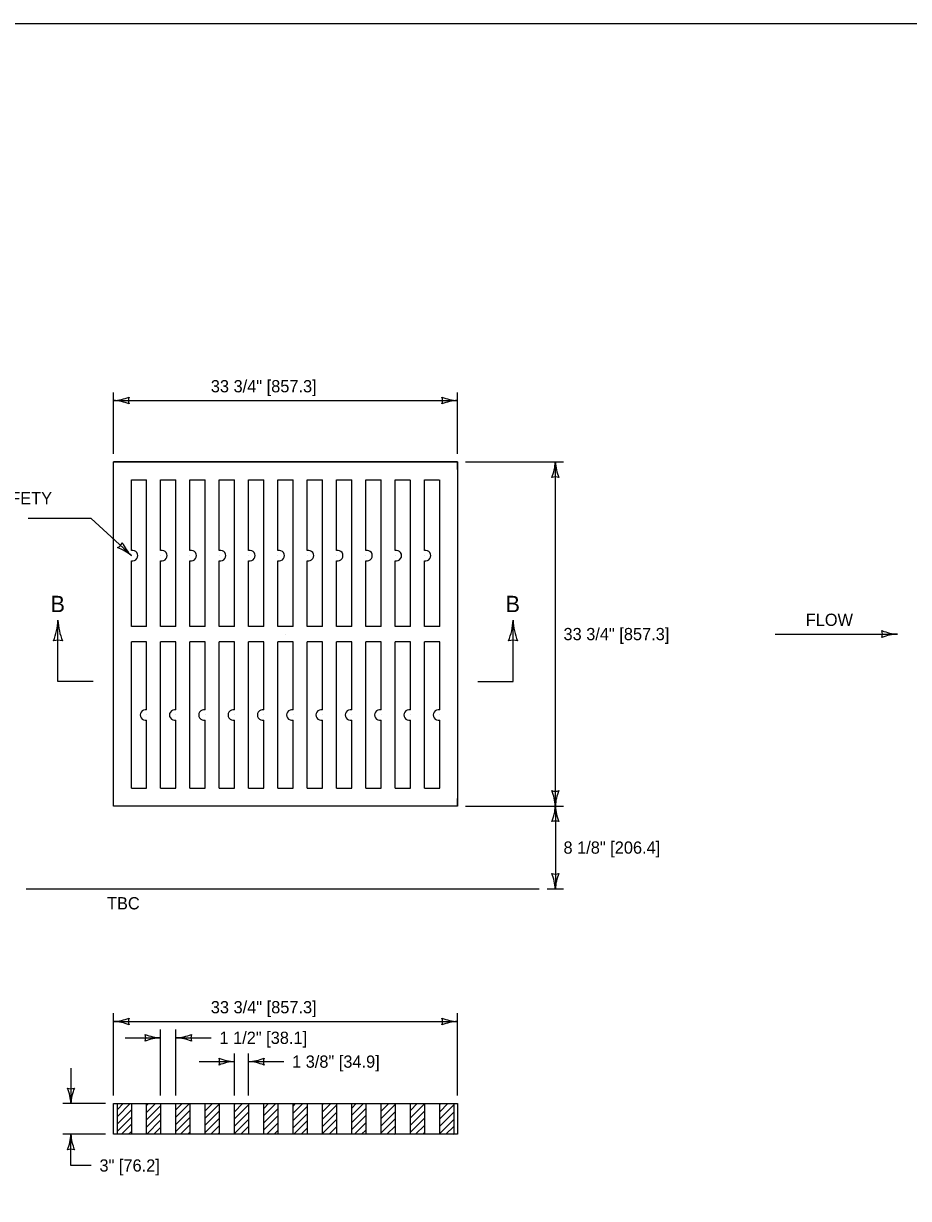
# Model space of a CAD drawing. Extents: x 49991.4 to 50041.6, y 49987.6 to 50011.4.
# Drawn here: x 50008.39 to 50012.74, y 49993.24 to 49999 of the extents above; entities that cross this region are included whole.
import ezdxf

# ---------------------------------------------------------------- set-up
doc = ezdxf.new("R2010")
doc.units = 0
for name, color, linetype in [('Level 1', 7, 'Continuous'), ('Level 2', 7, 'Continuous'), ('Level 3', 7, 'Continuous'), ('Level 6', 7, 'Continuous')]:
    doc.layers.add(name, color=color, linetype=linetype)

msp = doc.modelspace()

# ---------------------------------------------------------------- linework, layer by layer
at = {"layer": 'Level 1'}
for p, q in [((50010.5232, 49996.8492), (50008.8357, 49996.8492)), ((50008.8357, 49996.8117), (50008.8357, 49996.8492)), ((50008.8357, 49995.1617), (50008.8357, 49996.8492)), ((50008.8357, 49996.8492), (50010.5232, 49996.8492)), ((50010.5232, 49996.8117), (50010.5232, 49996.8492)), ((50010.5232, 49996.8492), (50010.5232, 49995.1617)), ((50008.9232, 49996.4149), (50008.9232, 49996.7617)), ((50008.9232, 49996.7617), (50008.9982, 49996.7617)), ((50008.9982, 49996.043), (50008.9982, 49996.7617)), ((50009.0669, 49996.4149), (50009.0669, 49996.7617)), ((50009.0669, 49996.7617), (50009.1419, 49996.7617)), ((50009.1419, 49996.043), (50009.1419, 49996.7617)), ((50009.2107, 49996.4149), (50009.2107, 49996.7617)), ((50009.2107, 49996.7617), (50009.2857, 49996.7617)), ((50009.2857, 49996.043), (50009.2857, 49996.7617)), ((50009.3544, 49996.4149), (50009.3544, 49996.7617)), ((50009.3544, 49996.7617), (50009.4294, 49996.7617)), ((50009.4294, 49996.043), (50009.4294, 49996.7617)), ((50009.4982, 49996.4149), (50009.4982, 49996.7617)), ((50009.4982, 49996.7617), (50009.5732, 49996.7617)), ((50009.5732, 49996.043), (50009.5732, 49996.7617)), ((50009.6419, 49996.4149), (50009.6419, 49996.7617)), ((50009.6419, 49996.7617), (50009.7169, 49996.7617)), ((50009.7169, 49996.043), (50009.7169, 49996.7617)), ((50009.7857, 49996.4149), (50009.7857, 49996.7617)), ((50009.7857, 49996.7617), (50009.8607, 49996.7617)), ((50009.8607, 49996.043), (50009.8607, 49996.7617)), ((50009.9294, 49996.4149), (50009.9294, 49996.7617)), ((50009.9294, 49996.7617), (50010.0044, 49996.7617)), ((50010.0044, 49996.043), (50010.0044, 49996.7617)), ((50010.0732, 49996.4149), (50010.0732, 49996.7617)), ((50010.0732, 49996.7617), (50010.1482, 49996.7617)), ((50010.1482, 49996.043), (50010.1482, 49996.7617)), ((50010.2169, 49996.4149), (50010.2169, 49996.7617)), ((50010.2169, 49996.7617), (50010.2888, 49996.7617)), ((50010.2919, 49996.043), (50010.2919, 49996.7617)), ((50010.3607, 49996.4149), (50010.3607, 49996.7617)), ((50010.3607, 49996.7617), (50010.4325, 49996.7617)), ((50010.4357, 49996.043), (50010.4357, 49996.7617)), ((50008.9232, 49996.3899), (50008.9232, 49996.3899)), ((50008.9232, 49996.043), (50008.9232, 49996.3649)), ((50009.0669, 49996.3899), (50009.0669, 49996.3899)), ((50009.0669, 49996.043), (50009.0669, 49996.3649)), ((50009.2107, 49996.3899), (50009.2107, 49996.3899)), ((50009.2107, 49996.043), (50009.2107, 49996.3649)), ((50009.3544, 49996.3899), (50009.3544, 49996.3899)), ((50009.3544, 49996.043), (50009.3544, 49996.3649)), ((50009.4982, 49996.3899), (50009.4982, 49996.3899)), ((50009.4982, 49996.043), (50009.4982, 49996.3649)), ((50009.6419, 49996.3899), (50009.6419, 49996.3899)), ((50009.6419, 49996.043), (50009.6419, 49996.3649)), ((50009.7857, 49996.3899), (50009.7857, 49996.3899)), ((50009.7857, 49996.043), (50009.7857, 49996.3649)), ((50009.9294, 49996.3899), (50009.9294, 49996.3899)), ((50009.9294, 49996.043), (50009.9294, 49996.3649)), ((50010.0732, 49996.3899), (50010.0732, 49996.3899)), ((50010.0732, 49996.043), (50010.0732, 49996.3649)), ((50010.2169, 49996.3899), (50010.2169, 49996.3899)), ((50010.2169, 49996.043), (50010.2169, 49996.3649)), ((50010.3607, 49996.3899), (50010.3607, 49996.3899)), ((50010.3607, 49996.043), (50010.3607, 49996.3649)), ((50008.9982, 49996.043), (50008.9232, 49996.043)), ((50009.1419, 49996.043), (50009.0669, 49996.043)), ((50009.2857, 49996.043), (50009.2107, 49996.043)), ((50009.4294, 49996.043), (50009.3544, 49996.043)), ((50009.5732, 49996.043), (50009.4982, 49996.043)), ((50009.7169, 49996.043), (50009.6419, 49996.043)), ((50009.6794, 49996.0055), (50009.6794, 49996.0055)), ((50009.8607, 49996.043), (50009.7857, 49996.043)), ((50010.0044, 49996.043), (50009.9294, 49996.043)), ((50010.1482, 49996.043), (50010.0732, 49996.043)), ((50010.2919, 49996.043), (50010.2169, 49996.043)), ((50010.4357, 49996.043), (50010.3607, 49996.043)), ((50008.9232, 49995.2492), (50008.9232, 49995.968)), ((50008.9982, 49995.968), (50008.9232, 49995.968)), ((50008.9982, 49995.6336), (50008.9982, 49995.968)), ((50009.0669, 49995.2492), (50009.0669, 49995.968)), ((50009.1419, 49995.968), (50009.0669, 49995.968)), ((50009.1419, 49995.6336), (50009.1419, 49995.968)), ((50009.2107, 49995.2492), (50009.2107, 49995.968)), ((50009.2857, 49995.968), (50009.2107, 49995.968)), ((50009.2857, 49995.6336), (50009.2857, 49995.968)), ((50009.3544, 49995.2492), (50009.3544, 49995.968)), ((50009.4294, 49995.968), (50009.3544, 49995.968)), ((50009.4294, 49995.6336), (50009.4294, 49995.968)), ((50009.4982, 49995.2492), (50009.4982, 49995.968)), ((50009.5732, 49995.968), (50009.4982, 49995.968)), ((50009.5732, 49995.6336), (50009.5732, 49995.968)), ((50009.6419, 49995.2492), (50009.6419, 49995.968)), ((50009.7169, 49995.968), (50009.6419, 49995.968)), ((50009.7169, 49995.6336), (50009.7169, 49995.968)), ((50009.7857, 49995.2492), (50009.7857, 49995.968)), ((50009.8607, 49995.968), (50009.7857, 49995.968)), ((50009.8607, 49995.6336), (50009.8607, 49995.968)), ((50009.9294, 49995.2492), (50009.9294, 49995.968)), ((50010.0044, 49995.968), (50009.9294, 49995.968)), ((50010.0044, 49995.6336), (50010.0044, 49995.968)), ((50010.0732, 49995.2492), (50010.0732, 49995.968)), ((50010.1482, 49995.968), (50010.0732, 49995.968)), ((50010.1482, 49995.6336), (50010.1482, 49995.968)), ((50010.2169, 49995.2492), (50010.2169, 49995.968)), ((50010.2919, 49995.968), (50010.2169, 49995.968)), ((50010.2919, 49995.6336), (50010.2919, 49995.968)), ((50010.3607, 49995.2492), (50010.3607, 49995.968)), ((50010.4357, 49995.968), (50010.3607, 49995.968)), ((50010.4357, 49995.6336), (50010.4357, 49995.968)), ((50008.9982, 49995.6086), (50008.9982, 49995.6086)), ((50009.1419, 49995.6086), (50009.1419, 49995.6086)), ((50009.2857, 49995.6086), (50009.2857, 49995.6086)), ((50009.4294, 49995.6086), (50009.4294, 49995.6086)), ((50009.5732, 49995.6086), (50009.5732, 49995.6086)), ((50009.7169, 49995.6086), (50009.7169, 49995.6086)), ((50009.8607, 49995.6086), (50009.8607, 49995.6086)), ((50010.0044, 49995.6086), (50010.0044, 49995.6086)), ((50010.1482, 49995.6086), (50010.1482, 49995.6086)), ((50010.2919, 49995.6086), (50010.2919, 49995.6086)), ((50010.4357, 49995.6086), (50010.4357, 49995.6086)), ((50008.9982, 49995.2492), (50008.9982, 49995.5836)), ((50009.1419, 49995.2492), (50009.1419, 49995.5836)), ((50009.2857, 49995.2492), (50009.2857, 49995.5836)), ((50009.4294, 49995.2492), (50009.4294, 49995.5836)), ((50009.5732, 49995.2492), (50009.5732, 49995.5836)), ((50009.7169, 49995.2492), (50009.7169, 49995.5836)), ((50009.8607, 49995.2492), (50009.8607, 49995.5836)), ((50010.0044, 49995.2492), (50010.0044, 49995.5836)), ((50010.1482, 49995.2492), (50010.1482, 49995.5836)), ((50010.2919, 49995.2492), (50010.2919, 49995.5836)), ((50010.4357, 49995.2492), (50010.4357, 49995.5836)), ((50008.8357, 49995.1617), (50008.8357, 49995.1992)), ((50008.9232, 49995.2492), (50008.9982, 49995.2492)), ((50009.0669, 49995.2492), (50009.1419, 49995.2492)), ((50009.2107, 49995.2492), (50009.2857, 49995.2492)), ((50009.3544, 49995.2492), (50009.4294, 49995.2492)), ((50009.4982, 49995.2492), (50009.5732, 49995.2492)), ((50009.6419, 49995.2492), (50009.7169, 49995.2492)), ((50009.7857, 49995.2492), (50009.8607, 49995.2492)), ((50009.9294, 49995.2492), (50010.0044, 49995.2492)), ((50010.0732, 49995.2492), (50010.1482, 49995.2492)), ((50010.2169, 49995.2492), (50010.2919, 49995.2492)), ((50010.3607, 49995.2492), (50010.4357, 49995.2492)), ((50010.5232, 49995.1617), (50010.5232, 49995.1992)), ((50010.5232, 49995.1617), (50008.8357, 49995.1617)), ((50010.5232, 49995.1617), (50008.8357, 49995.1617)), ((50008.4069, 49994.7555), (50010.9232, 49994.7555)), ((50008.8357, 49993.703), (50010.5232, 49993.703)), ((50008.8357, 49993.553), (50008.8357, 49993.703)), ((50008.8544, 49993.6393), (50008.9181, 49993.703)), ((50008.8544, 49993.6746), (50008.8828, 49993.703)), ((50008.9982, 49993.6589), (50009.0422, 49993.703)), ((50008.9982, 49993.6943), (50009.0069, 49993.703)), ((50009.1419, 49993.6365), (50009.2084, 49993.703)), ((50009.1419, 49993.6719), (50009.173, 49993.703)), ((50009.2857, 49993.6675), (50009.3211, 49993.703)), ((50009.2857, 49993.7029), (50009.2857, 49993.703)), ((50009.2857, 49993.6322), (50009.3544, 49993.7009)), ((50009.4294, 49993.6633), (50009.469, 49993.703)), ((50009.4294, 49993.6987), (50009.4337, 49993.703)), ((50009.4294, 49993.628), (50009.4982, 49993.6967)), ((50009.5732, 49993.6445), (50009.6316, 49993.703)), ((50009.5732, 49993.6799), (50009.5963, 49993.703)), ((50009.7169, 49993.6555), (50009.7644, 49993.703)), ((50009.7169, 49993.6908), (50009.729, 49993.703)), ((50009.8607, 49993.6623), (50009.9014, 49993.703)), ((50009.8607, 49993.6976), (50009.866, 49993.703)), ((50009.8607, 49993.6269), (50009.9294, 49993.6957)), ((50010.0044, 49993.6461), (50010.0613, 49993.703)), ((50010.0044, 49993.6814), (50010.0259, 49993.703)), ((50010.1482, 49993.6653), (50010.1858, 49993.703)), ((50010.1482, 49993.7006), (50010.1505, 49993.703)), ((50010.1482, 49993.6299), (50010.2169, 49993.6987)), ((50010.2919, 49993.6688), (50010.3261, 49993.703)), ((50010.2919, 49993.6334), (50010.3607, 49993.7022)), ((50010.4357, 49993.6633), (50010.4753, 49993.703)), ((50010.4357, 49993.6987), (50010.4399, 49993.703)), ((50010.4357, 49993.628), (50010.5044, 49993.6967)), ((50010.5232, 49993.703), (50010.5232, 49993.553)), ((50008.8544, 49993.6039), (50008.9232, 49993.6727)), ((50008.9982, 49993.6235), (50009.0669, 49993.6923)), ((50008.9982, 49993.5882), (50009.0669, 49993.6569)), ((50009.1419, 49993.6012), (50009.2107, 49993.6699)), ((50009.2857, 49993.5968), (50009.3544, 49993.6656)), ((50009.4294, 49993.5926), (50009.4982, 49993.6614)), ((50009.5732, 49993.6091), (50009.6419, 49993.6779)), ((50009.5732, 49993.5738), (50009.6419, 49993.6425)), ((50009.7169, 49993.6201), (50009.7857, 49993.6889)), ((50009.7169, 49993.5848), (50009.7857, 49993.6535)), ((50009.8607, 49993.5916), (50009.9294, 49993.6603)), ((50010.0044, 49993.6107), (50010.0732, 49993.6795)), ((50010.0044, 49993.5754), (50010.0732, 49993.6441)), ((50010.1482, 49993.5946), (50010.2169, 49993.6633)), ((50010.2919, 49993.5981), (50010.3607, 49993.6668)), ((50010.4357, 49993.5926), (50010.5044, 49993.6614)), ((50008.8544, 49993.5685), (50008.9232, 49993.6373)), ((50008.8742, 49993.553), (50008.9232, 49993.6019)), ((50008.9983, 49993.553), (50009.0669, 49993.6216)), ((50009.0336, 49993.553), (50009.0669, 49993.5862)), ((50009.1419, 49993.5658), (50009.2107, 49993.6345)), ((50009.1644, 49993.553), (50009.2107, 49993.5992)), ((50009.2857, 49993.5615), (50009.3544, 49993.6302)), ((50009.3125, 49993.553), (50009.3544, 49993.5949)), ((50009.4294, 49993.5573), (50009.4982, 49993.626)), ((50009.4605, 49993.553), (50009.4982, 49993.5907)), ((50009.5877, 49993.553), (50009.6419, 49993.6072)), ((50009.7205, 49993.553), (50009.7857, 49993.6182)), ((50009.7558, 49993.553), (50009.7857, 49993.5828)), ((50009.8607, 49993.5562), (50009.9294, 49993.625)), ((50009.8928, 49993.553), (50009.9294, 49993.5896)), ((50010.0174, 49993.553), (50010.0732, 49993.6088)), ((50010.1482, 49993.5592), (50010.2169, 49993.628)), ((50010.1773, 49993.553), (50010.2169, 49993.5926)), ((50010.2919, 49993.5627), (50010.3607, 49993.6315)), ((50010.3175, 49993.553), (50010.3607, 49993.5961)), ((50010.4357, 49993.5573), (50010.5044, 49993.626)), ((50010.4667, 49993.553), (50010.5044, 49993.5907)), ((50010.5232, 49993.553), (50008.8357, 49993.553)), ((50008.9095, 49993.553), (50008.9232, 49993.5666)), ((50009.1998, 49993.553), (50009.2107, 49993.5638)), ((50009.3479, 49993.553), (50009.3544, 49993.5595)), ((50009.4958, 49993.553), (50009.4982, 49993.5553)), ((50009.623, 49993.553), (50009.6419, 49993.5718)), ((50009.9281, 49993.553), (50009.9294, 49993.5542)), ((50010.0527, 49993.553), (50010.0732, 49993.5734)), ((50010.2126, 49993.553), (50010.2169, 49993.5573)), ((50010.3529, 49993.553), (50010.3607, 49993.5608)), ((50010.5021, 49993.553), (50010.5044, 49993.5553))]:
    msp.add_line(p, q, dxfattribs=at)
for points in [[(49999.3835, 49998.9992), (50016.7501, 49998.9992), (50016.7501, 49987.7988), (49999.3835, 49987.7988)], [(50008.8544, 49993.703), (50008.9232, 49993.703), (50008.9232, 49993.553), (50008.8544, 49993.553)], [(50008.9982, 49993.703), (50009.0669, 49993.703), (50009.0669, 49993.553), (50008.9982, 49993.553)], [(50009.1419, 49993.703), (50009.2107, 49993.703), (50009.2107, 49993.553), (50009.1419, 49993.553)], [(50009.2857, 49993.703), (50009.3544, 49993.703), (50009.3544, 49993.553), (50009.2857, 49993.553)], [(50009.4294, 49993.703), (50009.4982, 49993.703), (50009.4982, 49993.553), (50009.4294, 49993.553)], [(50009.5732, 49993.703), (50009.6419, 49993.703), (50009.6419, 49993.553), (50009.5732, 49993.553)], [(50009.7169, 49993.703), (50009.7857, 49993.703), (50009.7857, 49993.553), (50009.7169, 49993.553)], [(50009.8607, 49993.703), (50009.9294, 49993.703), (50009.9294, 49993.553), (50009.8607, 49993.553)], [(50010.0044, 49993.703), (50010.0732, 49993.703), (50010.0732, 49993.553), (50010.0044, 49993.553)], [(50010.1482, 49993.703), (50010.2169, 49993.703), (50010.2169, 49993.553), (50010.1482, 49993.553)], [(50010.2919, 49993.703), (50010.3607, 49993.703), (50010.3607, 49993.553), (50010.2919, 49993.553)], [(50010.4357, 49993.703), (50010.5044, 49993.703), (50010.5044, 49993.553), (50010.4357, 49993.553)]]:
    msp.add_lwpolyline(points, close=True, dxfattribs=at)
for centre, start, end in [((50008.9293, 49996.3899), 256.09409, 103.90591), ((50009.0731, 49996.3899), 256.09409, 103.90591), ((50009.2168, 49996.3899), 256.09409, 103.90591), ((50009.3606, 49996.3899), 256.09409, 103.90591), ((50009.5043, 49996.3899), 256.09409, 103.90591), ((50009.6481, 49996.3899), 256.09409, 103.90591), ((50009.7918, 49996.3899), 256.09409, 103.90591), ((50009.9356, 49996.3899), 256.09409, 103.90591), ((50010.0793, 49996.3899), 256.09409, 103.90591), ((50010.2231, 49996.3899), 256.09409, 103.90591), ((50010.3668, 49996.3899), 256.09409, 103.90591), ((50008.992, 49995.6086), 76.09409, 283.90591), ((50009.1357, 49995.6086), 76.09409, 283.90591), ((50009.2795, 49995.6086), 76.09409, 283.90591), ((50009.4232, 49995.6086), 76.09409, 283.90591), ((50009.567, 49995.6086), 76.09409, 283.90591), ((50009.7107, 49995.6086), 76.09409, 283.90591), ((50009.8545, 49995.6086), 76.09409, 283.90591), ((50009.9982, 49995.6086), 76.09409, 283.90591), ((50010.142, 49995.6086), 76.09409, 283.90591), ((50010.2857, 49995.6086), 76.09409, 283.90591), ((50010.4295, 49995.6086), 76.09409, 283.90591)]:
    msp.add_arc(centre, 0.0258, start, end, dxfattribs=at)
at = {"layer": 'Level 3'}
for p, q in [((50008.8357, 49996.8892), (50008.8357, 49997.1907)), ((50010.5232, 49996.8892), (50010.5232, 49997.1907)), ((50008.8357, 49997.1507), (50010.5232, 49997.1507)), ((50010.5632, 49996.8492), (50011.0432, 49996.8492)), ((50011.0032, 49995.1617), (50011.0032, 49996.8492)), ((50008.7265, 49996.5716), (50008.4169, 49996.5716)), ((50008.9232, 49996.3899), (50008.7265, 49996.5716)), ((50012.0814, 49996.0055), (50012.6814, 49996.0055)), ((50010.5632, 49995.1617), (50011.0432, 49995.1617)), ((50011.0032, 49995.1617), (50011.0032, 49994.7555)), ((50010.9632, 49994.7555), (50011.0432, 49994.7555)), ((50008.8357, 49993.743), (50008.8357, 49994.1459)), ((50008.8357, 49994.1059), (50010.5232, 49994.1059)), ((50010.5232, 49993.743), (50010.5232, 49994.1459)), ((50009.0669, 49993.743), (50009.0669, 49994.0659)), ((50009.1419, 49993.743), (50009.1419, 49994.0659)), ((50008.8935, 49994.0259), (50009.0669, 49994.0259)), ((50009.1419, 49994.0259), (50009.3153, 49994.0259)), ((50009.4294, 49993.743), (50009.4294, 49993.9491)), ((50009.4982, 49993.743), (50009.4982, 49993.9491)), ((50008.6267, 49993.8764), (50008.6267, 49993.703)), ((50009.256, 49993.9091), (50009.4294, 49993.9091)), ((50009.4982, 49993.9091), (50009.6716, 49993.9091)), ((50008.7957, 49993.703), (50008.5867, 49993.703)), ((50008.7957, 49993.553), (50008.5867, 49993.553)), ((50008.6267, 49993.3995), (50008.6267, 49993.553)), ((50008.7267, 49993.3995), (50008.6267, 49993.3995))]:
    msp.add_line(p, q, dxfattribs=at)
for centre, radius, start, end in [((50008.8242, 49997.3834), 0.233, 272.82731, 292.07716), ((50008.9639, 49997.1507), 0.0548, 162.13882, 197.86118), ((50010.5323, 49997.3728), 0.2223, 247.45601, 267.63952), ((50010.3949, 49997.1507), 0.0548, 342.13882, 17.86118), ((50008.8265, 49996.9285), 0.2223, 67.45601, 87.63952), ((50010.5346, 49996.918), 0.233, 92.82731, 112.07716), ((50010.781, 49996.8584), 0.2223, 337.45601, 357.63952), ((50011.2359, 49996.8607), 0.233, 182.82731, 202.07716), ((50011.0032, 49996.721), 0.0548, 72.13882, 107.86118), ((50008.829, 49996.4769), 0.0548, 299.41223, 335.13459), ((50008.7737, 49996.2111), 0.233, 50.10072, 69.35057), ((50009.0806, 49996.5468), 0.2223, 204.72942, 224.91293), ((50012.6906, 49996.2276), 0.2223, 247.45601, 267.63952), ((50012.5532, 49996.0055), 0.0548, 342.13882, 17.86118), ((50012.6929, 49995.7728), 0.233, 92.82731, 112.07716), ((50011.0032, 49995.29), 0.0548, 252.13882, 287.86118), ((50010.7704, 49995.1503), 0.233, 2.82731, 22.07716), ((50011.2253, 49995.1526), 0.2223, 157.45601, 177.63952), ((50010.781, 49995.1709), 0.2223, 337.45601, 357.63952), ((50011.2359, 49995.1732), 0.233, 182.82731, 202.07716), ((50011.0032, 49995.0335), 0.0548, 72.13882, 107.86118), ((50011.0032, 49994.8837), 0.0548, 252.13882, 287.86118), ((50010.7704, 49994.744), 0.233, 2.82731, 22.07716), ((50011.2253, 49994.7463), 0.2223, 157.45601, 177.63952), ((50008.8242, 49994.3386), 0.233, 272.82731, 292.07716), ((50008.8265, 49993.8837), 0.2223, 67.45601, 87.63952), ((50008.9639, 49994.1059), 0.0548, 162.13882, 197.86118), ((50010.5323, 49994.328), 0.2223, 247.45601, 267.63952), ((50010.3949, 49994.1059), 0.0548, 342.13882, 17.86118), ((50010.5346, 49993.8731), 0.233, 92.82731, 112.07716), ((50009.0761, 49994.248), 0.2223, 247.45601, 267.63952), ((50008.9387, 49994.0259), 0.0548, 342.13882, 17.86118), ((50009.1304, 49994.2586), 0.233, 272.82731, 292.07716), ((50009.2701, 49994.0259), 0.0548, 162.13882, 197.86118), ((50009.0784, 49993.7931), 0.233, 92.82731, 112.07716), ((50009.1327, 49993.8037), 0.2223, 67.45601, 87.63952), ((50009.4386, 49994.1312), 0.2223, 247.45601, 267.63952), ((50009.3012, 49993.9091), 0.0548, 342.13882, 17.86118), ((50009.4867, 49994.1418), 0.233, 272.82731, 292.07716), ((50009.6264, 49993.9091), 0.0548, 162.13882, 197.86118), ((50009.4409, 49993.6764), 0.233, 92.82731, 112.07716), ((50009.489, 49993.6869), 0.2223, 67.45601, 87.63952), ((50008.6267, 49993.8312), 0.0548, 252.13882, 287.86118), ((50008.394, 49993.6915), 0.233, 2.82731, 22.07716), ((50008.8489, 49993.6938), 0.2223, 157.45601, 177.63952), ((50008.4046, 49993.5621), 0.2223, 337.45601, 357.63952), ((50008.8594, 49993.5645), 0.233, 182.82731, 202.07716), ((50008.6267, 49993.4247), 0.0548, 72.13882, 107.86118)]:
    msp.add_arc(centre, radius, start, end, dxfattribs=at)
at = {"layer": 'Level 6'}
for p, q in [((50008.5632, 49995.773), (50008.5632, 49996.073)), ((50010.7957, 49995.773), (50010.7957, 49996.073)), ((50008.7357, 49995.773), (50008.5632, 49995.773)), ((50010.6232, 49995.773), (50010.7957, 49995.773))]:
    msp.add_line(p, q, dxfattribs=at)
for centre, radius, start, end in [((50008.267, 49996.0852), 0.2964, 337.45601, 357.63952), ((50008.8734, 49996.0883), 0.3107, 182.82731, 202.07716), ((50010.4995, 49996.0852), 0.2964, 337.45601, 357.63952), ((50011.1059, 49996.0883), 0.3107, 182.82731, 202.07716), ((50008.5632, 49995.902), 0.073, 72.13882, 107.86118), ((50010.7957, 49995.902), 0.073, 72.13882, 107.86118)]:
    msp.add_arc(centre, radius, start, end, dxfattribs=at)

# ---------------------------------------------------------------- texts
at = {"layer": 'Level 2'}
for s, height, p in [('33 3/4" [857.3]', 0.06, (50009.313, 49997.1907)), ('SAFETY', 0.06, (50008.2221, 49996.6418)), ('B', 0.08, (50008.5261, 49996.113)), ('B', 0.08, (50010.7586, 49996.113)), ('FLOW', 0.06, (50012.2316, 49996.0455)), ('33 3/4" [857.3]', 0.06, (50011.0432, 49995.9755)), ('8 1/8" [206.4]', 0.06, (50011.0432, 49994.9286)), ('TBC', 0.06, (50008.8037, 49994.6555)), ('33 3/4" [857.3]', 0.06, (50009.313, 49994.1459)), ('1 1/2" [38.1]', 0.06, (50009.3553, 49993.9959)), ('1 3/8" [34.9]', 0.06, (50009.7116, 49993.8791)), ('3" [76.2]', 0.06, (50008.7667, 49993.3697))]:
    msp.add_text(s, height=height, dxfattribs=at).set_placement(p)

doc.saveas('drawing.dxf')
